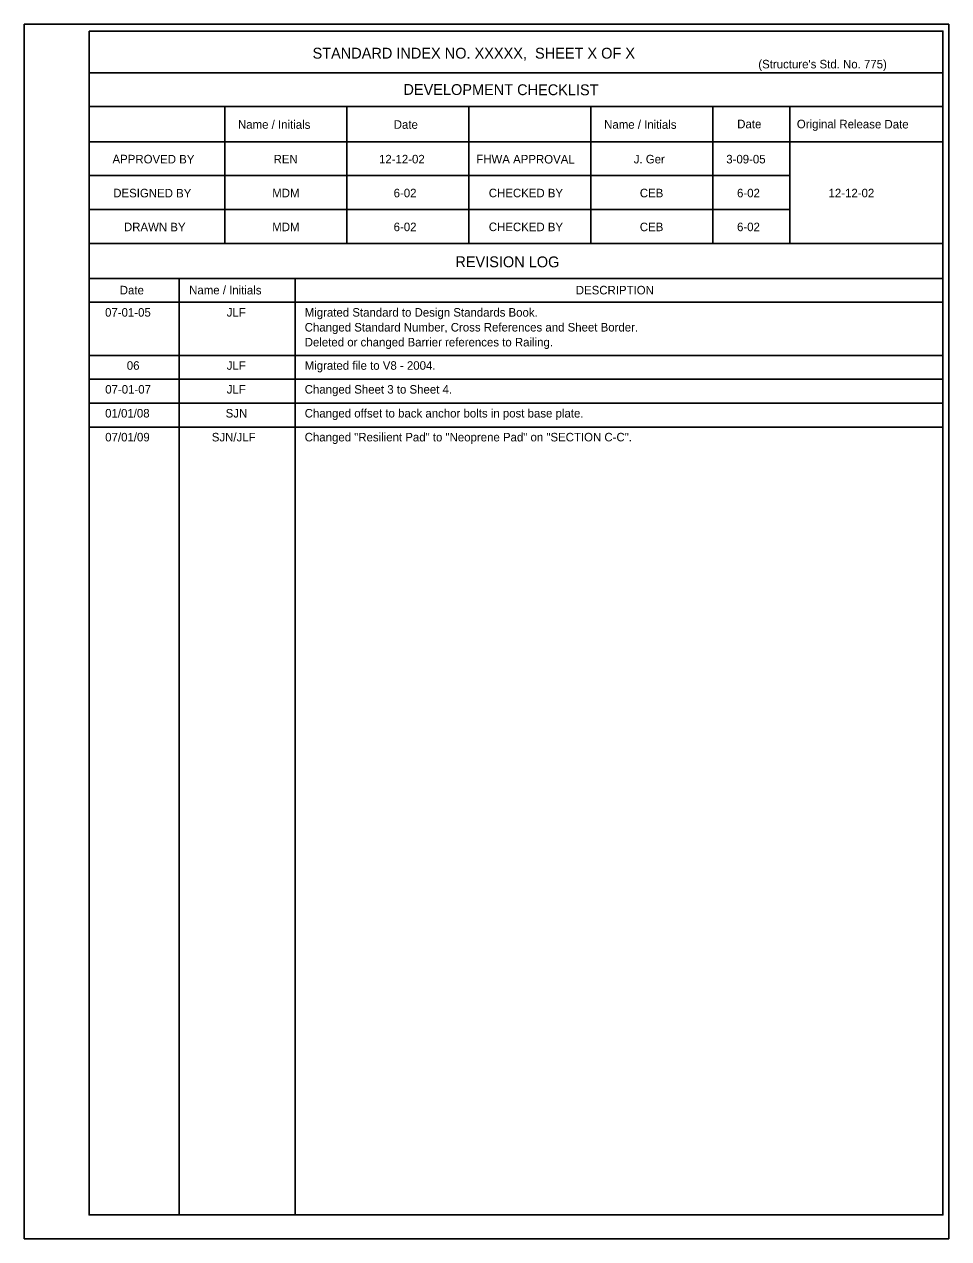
# Model space of a CAD drawing. Extents: x 21652.5 to 21723.2, y 56079.2 to 56117.9.
# Drawn here: x 21701.34 to 21723.15, y 56085.51 to 56114.17 of the extents above; entities that cross this region are included whole.
import ezdxf

# ---------------------------------------------------------------- set-up
doc = ezdxf.new("R2010")
doc.units = 0
for name, color, linetype in [('Border', 7, 'Continuous'), ('Dimension', 7, 'Continuous'), ('PlotBorder_dp', 7, 'Continuous'), ('TextStructures', 7, 'Continuous')]:
    doc.layers.add(name, color=color, linetype=linetype)

msp = doc.modelspace()

# ---------------------------------------------------------------- linework, layer by layer
at = {"layer": 'Border'}
for p, q in [((21723.018, 56113.031), (21702.871, 56113.031)), ((21723.018, 56112.231), (21702.871, 56112.231)), ((21706.071, 56112.231), (21706.071, 56109.003)), ((21708.951, 56112.231), (21708.951, 56109.003)), ((21711.831, 56112.231), (21711.831, 56109.003)), ((21714.711, 56112.231), (21714.711, 56109.003)), ((21717.591, 56112.231), (21717.591, 56109.003)), ((21719.406, 56112.231), (21719.406, 56109.003)), ((21723.018, 56111.403), (21702.871, 56111.403)), ((21719.406, 56110.603), (21702.871, 56110.603)), ((21719.406, 56109.803), (21702.871, 56109.803)), ((21723.018, 56109.003), (21702.871, 56109.003)), ((21723.018, 56108.175), (21702.871, 56108.175)), ((21704.991, 56108.175), (21704.991, 56086.069)), ((21707.733, 56108.175), (21707.733, 56086.069)), ((21723.018, 56107.612), (21702.871, 56107.612))]:
    msp.add_line(p, q, dxfattribs=at)
msp.add_lwpolyline([(21702.871, 56114.012), (21723.018, 56114.012), (21723.018, 56086.069), (21702.871, 56086.069)], close=True, dxfattribs=at)
at = {"layer": 'Dimension'}
for p, q in [((21702.871, 56106.357), (21723.018, 56106.357)), ((21702.871, 56105.794), (21723.018, 56105.794)), ((21702.871, 56105.23), (21723.018, 56105.23)), ((21702.871, 56104.666), (21723.018, 56104.666))]:
    msp.add_line(p, q, dxfattribs=at)
at = {"layer": 'PlotBorder_dp'}
msp.add_line((21701.34, 56085.508), (21701.34, 56085.508), dxfattribs=at)
msp.add_lwpolyline([(21701.34, 56114.174), (21723.154, 56114.174), (21723.154, 56085.508), (21701.34, 56085.508)], close=True, dxfattribs=at)

# ---------------------------------------------------------------- texts
at = {"layer": 'TextStructures'}
for s, height, p in [('STANDARD INDEX NO. XXXXX,  SHEET X OF X', 0.256, (21708.142, 56113.364)), ("(Structure's Std. No. 775)", 0.2016, (21718.661, 56113.133)), ('REN', 0.2016, (21707.223, 56110.89)), ('12-12-02', 0.2016, (21709.71, 56110.89)), ('J. Ger', 0.2016, (21715.721, 56110.89)), ('3-09-05', 0.2016, (21717.904, 56110.89)), ('MDM', 0.2016, (21707.191, 56110.09)), ('6-02', 0.2016, (21710.056, 56110.09)), ('CEB', 0.2016, (21715.865, 56110.09)), ('6-02', 0.2016, (21718.159, 56110.09)), ('12-12-02', 0.2016, (21720.318, 56110.09)), ('MDM', 0.2016, (21707.191, 56109.29)), ('6-02', 0.2016, (21710.056, 56109.29)), ('CEB', 0.2016, (21715.865, 56109.29)), ('6-02', 0.2016, (21718.159, 56109.29)), ('DESCRIPTION', 0.2016, (21714.354, 56107.798)), ('07-01-05', 0.2016, (21703.246, 56107.273)), ('JLF', 0.2016, (21706.117, 56107.273)), ('Migrated Standard to Design Standards Book.', 0.2016, (21707.957, 56107.273)), ('Changed Standard Number, Cross References and Sheet Border.', 0.2016, (21707.957, 56106.922)), ('Deleted or changed Barrier references to Railing.', 0.2016, (21707.957, 56106.57)), ('06', 0.2016, (21703.759, 56106.019)), ('JLF', 0.2016, (21706.117, 56106.019)), ('Migrated file to V8 - 2004.', 0.2016, (21707.957, 56106.019)), ('07-01-07', 0.2016, (21703.25, 56105.456)), ('JLF', 0.2016, (21706.117, 56105.456)), ('Changed Sheet 3 to Sheet 4.', 0.2016, (21707.957, 56105.456)), ('01/01/08', 0.2016, (21703.248, 56104.892)), ('SJN', 0.2016, (21706.092, 56104.892)), ('Changed offset to back anchor bolts in post base plate.', 0.2016, (21707.957, 56104.892)), ('07/01/09', 0.2016, (21703.25, 56104.328)), ('SJN/JLF', 0.2016, (21705.765, 56104.328)), ('Changed "Resilient Pad" to "Neoprene Pad" on "SECTION C-C". ', 0.2016, (21707.957, 56104.328))]:
    msp.add_text(s, height=height, dxfattribs=at).set_placement(p)
for s, height, p in [('DEVELOPMENT CHECKLIST', 0.256, (21710.287, 56112.508)), ('Name / Initials', 0.2016, (21706.383, 56111.71)), ('Date', 0.2016, (21710.058, 56111.708)), ('Name / Initials', 0.2016, (21715.023, 56111.71)), ('Date', 0.2016, (21718.163, 56111.72)), ('Original Release Date', 0.2016, (21719.57, 56111.72)), ('APPROVED BY', 0.2016, (21703.422, 56110.892)), ('FHWA APPROVAL', 0.2016, (21712.006, 56110.892)), ('DESIGNED BY', 0.2016, (21703.439, 56110.09)), ('CHECKED BY', 0.2016, (21712.301, 56110.092)), ('DRAWN BY', 0.2016, (21703.692, 56109.29)), ('CHECKED BY', 0.2016, (21712.301, 56109.292)), ('REVISION LOG', 0.256, (21711.512, 56108.442)), ('Name / Initials', 0.2016, (21705.23, 56107.801)), ('Date', 0.2016, (21703.593, 56107.799))]:
    msp.add_text(s, height=height, rotation=359.8756, dxfattribs=at).set_placement(p)

doc.saveas('drawing.dxf')
